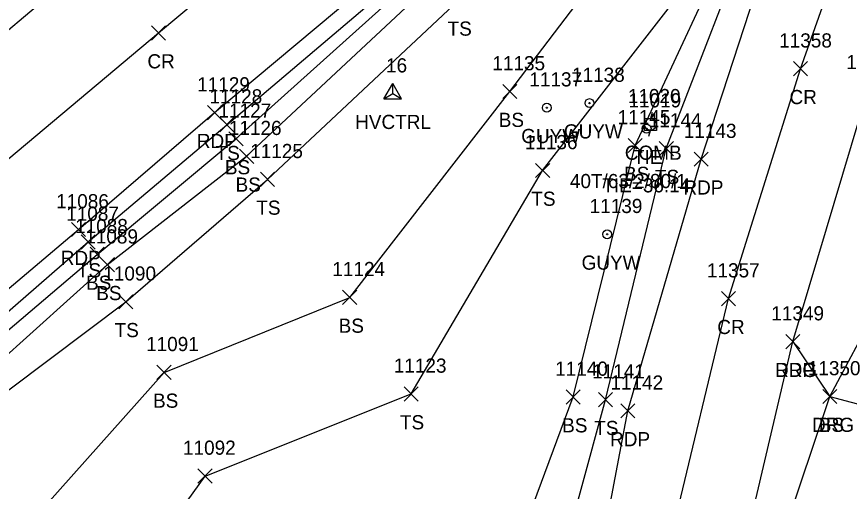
# Model space of a CAD drawing. Extents: x 1475671 to 1477951, y 592661 to 593821.
# Drawn here: x 1476740.9 to 1476858.4, y 593196.5 to 593263.5 of the extents above; entities that cross this region are included whole.
import ezdxf

# ---------------------------------------------------------------- set-up
doc = ezdxf.new("R2010")
doc.units = 0
for name, color, linetype in [('C_A', 7, 'Continuous'), ('C_C', 7, 'Continuous'), ('C_I', 7, 'Continuous'), ('CBP', 7, 'Continuous'), ('CPSM', 7, 'Continuous'), ('L_A', 7, 'Continuous'), ('L_I', 7, 'Continuous'), ('L_TIC', 7, 'Continuous'), ('LELB', 7, 'Continuous'), ('P_A', 7, 'Continuous'), ('P_I', 7, 'Continuous'), ('P_TIC', 7, 'Continuous'), ('PET', 7, 'Continuous'), ('PRC', 7, 'Continuous'), ('R_A', 7, 'Continuous'), ('R_I', 7, 'Continuous'), ('R_TIC', 7, 'Continuous'), ('RDG', 7, 'Continuous'), ('U_A', 7, 'Continuous'), ('U_C', 7, 'Continuous'), ('U_I', 7, 'Continuous'), ('UP', 7, 'Continuous'), ('UPGW', 7, 'Continuous')]:
    doc.layers.add(name, color=color, linetype=linetype)

msp = doc.modelspace()

# ---------------------------------------------------------------- linework, layer by layer
at = {"layer": 'CBP'}
for radius in [0.625, 0.0833]:
    msp.add_circle((1476829.76, 593247.7), radius, dxfattribs=at)
at = {"layer": 'CPSM'}
for p, q in [((1476792.7, 593251.92), (1476793.95, 593254.09)), ((1476792.7, 593251.92), (1476793.95, 593254.09)), ((1476792.7, 593251.92), (1476793.95, 593254.09)), ((1476792.7, 593251.92), (1476793.95, 593254.09)), ((1476792.7, 593251.92), (1476793.95, 593254.09)), ((1476792.7, 593251.92), (1476793.95, 593254.09)), ((1476792.7, 593251.92), (1476793.95, 593254.09)), ((1476792.7, 593251.92), (1476793.95, 593254.09)), ((1476795.2, 593251.92), (1476793.95, 593254.09)), ((1476793.95, 593252.65), (1476793.95, 593254.09)), ((1476795.2, 593251.92), (1476793.95, 593254.09)), ((1476793.95, 593252.65), (1476793.95, 593254.09)), ((1476795.2, 593251.92), (1476793.95, 593254.09)), ((1476793.95, 593252.65), (1476793.95, 593254.09)), ((1476795.2, 593251.92), (1476793.95, 593254.09)), ((1476793.95, 593252.65), (1476793.95, 593254.09)), ((1476795.2, 593251.92), (1476793.95, 593254.09)), ((1476793.95, 593252.65), (1476793.95, 593254.09)), ((1476795.2, 593251.92), (1476793.95, 593254.09)), ((1476793.95, 593252.65), (1476793.95, 593254.09)), ((1476795.2, 593251.92), (1476793.95, 593254.09)), ((1476793.95, 593252.65), (1476793.95, 593254.09)), ((1476795.2, 593251.92), (1476793.95, 593254.09)), ((1476793.95, 593252.65), (1476793.95, 593254.09)), ((1476792.7, 593251.92), (1476793.95, 593252.65)), ((1476792.7, 593251.92), (1476793.95, 593252.65)), ((1476792.7, 593251.92), (1476793.95, 593252.65)), ((1476792.7, 593251.92), (1476793.95, 593252.65)), ((1476792.7, 593251.92), (1476793.95, 593252.65)), ((1476792.7, 593251.92), (1476793.95, 593252.65)), ((1476792.7, 593251.92), (1476793.95, 593252.65)), ((1476792.7, 593251.92), (1476793.95, 593252.65)), ((1476792.7, 593251.92), (1476795.2, 593251.92)), ((1476792.7, 593251.92), (1476795.2, 593251.92)), ((1476792.7, 593251.92), (1476795.2, 593251.92)), ((1476792.7, 593251.92), (1476795.2, 593251.92)), ((1476792.7, 593251.92), (1476795.2, 593251.92)), ((1476792.7, 593251.92), (1476795.2, 593251.92)), ((1476792.7, 593251.92), (1476795.2, 593251.92)), ((1476792.7, 593251.92), (1476795.2, 593251.92)), ((1476793.95, 593252.65), (1476793.95, 593252.65)), ((1476793.95, 593252.65), (1476795.2, 593251.92)), ((1476793.95, 593252.65), (1476793.95, 593252.65)), ((1476793.95, 593252.65), (1476795.2, 593251.92)), ((1476793.95, 593252.65), (1476793.95, 593252.65)), ((1476793.95, 593252.65), (1476795.2, 593251.92)), ((1476793.95, 593252.65), (1476793.95, 593252.65)), ((1476793.95, 593252.65), (1476795.2, 593251.92)), ((1476793.95, 593252.65), (1476793.95, 593252.65)), ((1476793.95, 593252.65), (1476795.2, 593251.92)), ((1476793.95, 593252.65), (1476793.95, 593252.65)), ((1476793.95, 593252.65), (1476795.2, 593251.92)), ((1476793.95, 593252.65), (1476793.95, 593252.65)), ((1476793.95, 593252.65), (1476795.2, 593251.92)), ((1476793.95, 593252.65), (1476793.95, 593252.65)), ((1476793.95, 593252.65), (1476795.2, 593251.92))]:
    msp.add_line(p, q, dxfattribs=at)
at = {"layer": 'L_TIC'}
for points in [[(1476809.46, 593251.94), (1476811.46, 593253.94)], [(1476811.46, 593251.94), (1476809.46, 593253.94)], [(1476769.54, 593247.26), (1476771.54, 593249.26)], [(1476771.54, 593247.26), (1476769.54, 593249.26)], [(1476770.82, 593245.25), (1476772.82, 593247.25)], [(1476772.82, 593245.25), (1476770.82, 593247.25)], [(1476827.14, 593244.31), (1476829.14, 593246.31)], [(1476829.14, 593244.31), (1476827.14, 593246.31)], [(1476772.33, 593242.8), (1476774.33, 593244.8)], [(1476774.33, 593242.8), (1476772.33, 593244.8)], [(1476831.54, 593243.88), (1476833.54, 593245.88)], [(1476833.54, 593243.88), (1476831.54, 593245.88)], [(1476814.09, 593240.8), (1476816.09, 593242.8)], [(1476816.09, 593240.8), (1476814.09, 593242.8)], [(1476775.28, 593239.54), (1476777.28, 593241.54)], [(1476777.28, 593239.54), (1476775.28, 593241.54)], [(1476749.98, 593230.69), (1476751.98, 593232.69)], [(1476751.98, 593230.69), (1476749.98, 593232.69)], [(1476751.23, 593228.94), (1476753.23, 593230.94)], [(1476753.23, 593228.94), (1476751.23, 593230.94)], [(1476752.67, 593227.48), (1476754.67, 593229.48)], [(1476754.67, 593227.48), (1476752.67, 593229.48)], [(1476786.87, 593222.87), (1476788.87, 593224.87)], [(1476788.87, 593222.87), (1476786.87, 593224.87)], [(1476755.29, 593222.25), (1476757.29, 593224.25)], [(1476757.29, 593222.25), (1476755.29, 593224.25)], [(1476760.68, 593212.28), (1476762.68, 593214.28)], [(1476762.68, 593212.28), (1476760.68, 593214.28)], [(1476795.55, 593209.23), (1476797.55, 593211.23)], [(1476797.55, 593209.23), (1476795.55, 593211.23)], [(1476818.41, 593208.8), (1476820.41, 593210.8)], [(1476820.41, 593208.8), (1476818.41, 593210.8)], [(1476854.62, 593208.87), (1476856.62, 593210.87)], [(1476856.62, 593208.87), (1476854.62, 593210.87)], [(1476822.97, 593208.42), (1476824.97, 593210.42)], [(1476824.97, 593208.42), (1476822.97, 593210.42)], [(1476766.46, 593197.64), (1476768.46, 593199.64)], [(1476768.46, 593197.64), (1476766.46, 593199.64)]]:
    msp.add_lwpolyline(points, dxfattribs=at)
at = {"layer": 'LELB'}
for points in [[(1476844.89, 593161.77), (1476849.57, 593180.8), (1476849.13, 593190.54), (1476855.62, 593209.87), (1476862.35, 593222.47), (1476869.87, 593249.68), (1476878.56, 593271.73), (1476877.88, 593280.96), (1476889.82, 593301.6), (1476893.1, 593318.84), (1476908.59, 593341.2), (1476918.55, 593355.38), (1476919.84, 593361.76), (1476917.93, 593365.87), (1476921.61, 593367.66), (1476922.08, 593366.69), (1476922.63, 593360.35), (1476925.59, 593366.62)], [(1476564.12, 593090.41), (1476582.11, 593100.23), (1476611.48, 593121.39), (1476618.84, 593125.52), (1476623.35, 593128.86), (1476625.72, 593132.79), (1476629.36, 593135.67), (1476655.41, 593152.72), (1476679.21, 593171.49), (1476707, 593193.97), (1476724.55, 593208.7), (1476750.98, 593231.69), (1476770.54, 593248.26), (1476798.66, 593272.17), (1476825.82, 593296.2), (1476846.6, 593313.13), (1476851.35, 593312.9), (1476856.13, 593310.72)], [(1476716.34, 593096.61), (1476747.99, 593101.23), (1476767.4, 593103.17), (1476784.21, 593098.41), (1476795.95, 593095.07), (1476817.54, 593090.06), (1476823.68, 593097.1), (1476820.13, 593119.71), (1476817.83, 593141.9), (1476818.22, 593150.2), (1476818.44, 593161.48), (1476817.39, 593176.1), (1476816.81, 593183.14), (1476823.97, 593209.42), (1476832.54, 593244.88), (1476845.72, 593279.11), (1476851.19, 593296.52), (1476856.13, 593310.72)], [(1476634.2, 593131.94), (1476659.65, 593146.95), (1476682.12, 593166.73), (1476708.67, 593192.24), (1476725.71, 593207.35), (1476752.23, 593229.94), (1476771.82, 593246.25), (1476799.29, 593271), (1476827.81, 593293.85), (1476847.08, 593308.34), (1476849.31, 593306.85)], [(1476637.68, 593129.04), (1476661.51, 593144.5), (1476683.5, 593163.51), (1476710.24, 593189.5), (1476727.5, 593204.94), (1476753.67, 593228.48), (1476773.33, 593243.8), (1476800.69, 593269.42), (1476829.36, 593291.34), (1476849.31, 593306.85)], [(1476656.28, 593095.98), (1476668.8, 593096.98), (1476674.42, 593093.25), (1476681.71, 593092.91), (1476715.01, 593104.2), (1476743.41, 593111.46), (1476771.5, 593107.28), (1476782.77, 593105.35), (1476795.28, 593099.97), (1476811.26, 593100.05), (1476809.57, 593119.11), (1476813.36, 593153.77), (1476804.91, 593159.06), (1476804.56, 593163.8), (1476803.63, 593168.61), (1476810.96, 593186.98), (1476819.41, 593209.8), (1476828.14, 593245.31), (1476843.63, 593278.61), (1476845.71, 593295.92), (1476849.31, 593306.85)], [(1476678.64, 593101), (1476705.61, 593123.8), (1476726.04, 593155.11), (1476737.72, 593186.36), (1476761.68, 593213.28), (1476787.87, 593223.87), (1476810.46, 593252.94), (1476833.91, 593283.76), (1476845.71, 593295.92)], [(1476656.22, 593100.09), (1476649.63, 593114.77), (1476646.3, 593117.93), (1476646.01, 593122.62), (1476642.33, 593128.21), (1476662.9, 593142.59), (1476684.96, 593160.73), (1476712.65, 593184.75), (1476728.9, 593202.65), (1476756.29, 593223.25), (1476776.28, 593240.54), (1476803.27, 593265.83), (1476831.65, 593287.61)], [(1476678.64, 593101), (1476711, 593115.17), (1476731.22, 593143.42), (1476747.62, 593171.01), (1476767.46, 593198.64), (1476796.55, 593210.23), (1476815.09, 593241.8), (1476843.63, 593278.61)]]:
    msp.add_lwpolyline(points, dxfattribs=at)
at = {"layer": 'P_TIC'}
for points in [[(1476759.9, 593260.21), (1476761.9, 593262.21)], [(1476761.9, 593260.21), (1476759.9, 593262.21)], [(1476850.49, 593255.16), (1476852.49, 593257.16)], [(1476852.49, 593255.16), (1476850.49, 593257.16)], [(1476767.81, 593248.96), (1476769.81, 593250.96)], [(1476769.81, 593248.96), (1476767.81, 593250.96)], [(1476836.47, 593242.39), (1476838.47, 593244.39)], [(1476838.47, 593242.39), (1476836.47, 593244.39)], [(1476748.61, 593232.45), (1476750.61, 593234.45)], [(1476750.61, 593232.45), (1476748.61, 593234.45)], [(1476840.31, 593222.69), (1476842.31, 593224.69)], [(1476842.31, 593222.69), (1476840.31, 593224.69)], [(1476849.39, 593216.62), (1476851.39, 593218.62)], [(1476851.39, 593216.62), (1476849.39, 593218.62)], [(1476826.12, 593206.84), (1476828.12, 593208.84)], [(1476828.12, 593206.84), (1476826.12, 593208.84)]]:
    msp.add_lwpolyline(points, dxfattribs=at)
at = {"layer": 'PET'}
for points in [[(1476493.61, 593061.9), (1476518.9, 593073.26), (1476550.12, 593088.22), (1476579.1, 593105.35), (1476612.57, 593127.79), (1476627.64, 593138.01), (1476653.65, 593155.86), (1476677.37, 593174.62), (1476705.43, 593196.67), (1476722.66, 593210.69), (1476749.61, 593233.45), (1476768.81, 593249.96), (1476797.5, 593274.02), (1476824.82, 593297.55), (1476845, 593315.29), (1476868.19, 593333.86), (1476888.66, 593352.98), (1476918.01, 593376.95), (1476944.23, 593398.87), (1476967.73, 593418.7), (1476998.53, 593444.47)], [(1476459.25, 593078.48), (1476508.39, 593100.17), (1476518.15, 593105.13), (1476565.38, 593131.07), (1476607.43, 593157.45), (1476640.25, 593180.54), (1476678.21, 593210.57), (1476708.64, 593235.75), (1476725.67, 593249.83), (1476755.84, 593275.3), (1476786.3, 593300.73), (1476814.32, 593324.28), (1476845.05, 593350.02), (1476865.02, 593366.82), (1476897.04, 593395.14), (1476922.98, 593419.08), (1476952.36, 593443.37)], [(1476852.05, 593085.53), (1476845.73, 593108.15), (1476841.01, 593134.78), (1476840.06, 593162.08), (1476843.4, 593187.72), (1476850.39, 593217.62), (1476860.98, 593253.11), (1476864.6, 593261.54), (1476871.79, 593281.35), (1476880.28, 593307.27), (1476885.63, 593321.18), (1476897.83, 593348.03), (1476918.01, 593376.95)], [(1476550.12, 593088.22), (1476546.99, 593080.79), (1476546.62, 593074.3), (1476558.02, 593070.45), (1476566.6, 593070.83), (1476605.7, 593074.02), (1476651.65, 593078.89), (1476683.81, 593086.28), (1476716.78, 593091.72), (1476756.3, 593096.32), (1476786.76, 593094.61), (1476795.52, 593092.66), (1476816.88, 593085.29), (1476835.43, 593074.22), (1476828.62, 593102.02), (1476824.42, 593119.75), (1476821.59, 593140.77), (1476821.02, 593163.56), (1476821.92, 593180.44), (1476827.12, 593207.84), (1476837.47, 593243.39), (1476848.83, 593278.3), (1476858.44, 593303.19), (1476868.19, 593333.86)]]:
    msp.add_lwpolyline(points, dxfattribs=at)
at = {"layer": 'PRC'}
for points in [[(1476461.98, 593064.62), (1476520.7, 593090.52), (1476540.79, 593101.34), (1476577.67, 593121.61), (1476614.51, 593145.69), (1476649.36, 593170.81), (1476687.02, 593200.01), (1476716.69, 593224.25), (1476733.58, 593238.31), (1476760.9, 593261.21), (1476795.35, 593290.14), (1476823.06, 593313.51), (1476854.07, 593339.52), (1476875.7, 593357.51), (1476907.01, 593384.08), (1476934.06, 593407.68), (1476963.46, 593432.81)], [(1476853.41, 593046.52), (1476841.6, 593084.28), (1476835.78, 593107.15), (1476831.7, 593132.51), (1476830.84, 593162.78), (1476833.45, 593190.92), (1476841.31, 593223.69), (1476851.49, 593256.16), (1476861.32, 593283.91), (1476867.45, 593299.57), (1476876.22, 593323.15), (1476888.66, 593352.98)]]:
    msp.add_lwpolyline(points, dxfattribs=at)
at = {"layer": 'R_TIC'}
for points in [[(1476849.39, 593216.62), (1476851.39, 593218.62)], [(1476851.39, 593216.62), (1476849.39, 593218.62)], [(1476854.62, 593208.87), (1476856.62, 593210.87)], [(1476856.62, 593208.87), (1476854.62, 593210.87)]]:
    msp.add_lwpolyline(points, dxfattribs=at)
at = {"layer": 'RDG'}
msp.add_lwpolyline([(1476850.39, 593217.62), (1476855.62, 593209.87), (1476871.37, 593205.7), (1476882.63, 593203.65), (1476898.32, 593201.52), (1476908.1, 593203.87), (1476921.63, 593214.39), (1476929.61, 593231.45), (1476934.18, 593252.23), (1476938.78, 593270.03), (1476944.38, 593296.1), (1476944.94, 593325.58), (1476942.87, 593338.88), (1476933.5, 593367.74), (1476927.3, 593373.86), (1476918.01, 593376.95)], dxfattribs=at)
at = {"layer": 'UP'}
for p, q in [((1476830.56, 593249.96), (1476830.31, 593249.13)), ((1476829.47, 593247.46), (1476829.47, 593249.13)), ((1476829.47, 593249.13), (1476831.14, 593249.13)), ((1476830.31, 593248.3), (1476830.31, 593248.3)), ((1476831.14, 593249.13), (1476831.14, 593247.46)), ((1476831.14, 593247.46), (1476829.47, 593247.46)), ((1476830.06, 593246.63), (1476830.31, 593247.46))]:
    msp.add_line(p, q, dxfattribs=at)
msp.add_circle((1476830.31, 593248.3), 0.833, dxfattribs=at)
at = {"layer": 'UPGW'}
for centre, radius in [((1476821.7, 593251.31), 0.625), ((1476815.68, 593250.66), 0.625), ((1476815.68, 593250.66), 0.0833), ((1476821.7, 593251.31), 0.0833), ((1476824.2, 593232.78), 0.625), ((1476824.2, 593232.78), 0.0833)]:
    msp.add_circle(centre, radius, dxfattribs=at)

# ---------------------------------------------------------------- texts
at = {"layer": 'C_A'}
for s, p in [('HVCTRL', (1476788.64, 593247.65)), ('HVCTRL', (1476788.64, 593247.65)), ('HVCTRL', (1476788.64, 593247.65)), ('HVCTRL', (1476788.64, 593247.65)), ('HVCTRL', (1476788.64, 593247.65)), ('HVCTRL', (1476788.64, 593247.65)), ('HVCTRL', (1476788.64, 593247.65)), ('HVCTRL', (1476788.64, 593247.65)), ('TIE', (1476827.84, 593242.7))]:
    msp.add_text(s, height=2, dxfattribs=at).set_placement(p)
at = {"layer": 'C_C'}
msp.add_text('TIE=36.14', height=2, dxfattribs=at).set_placement((1476823.51, 593238.7))
at = {"layer": 'C_I'}
for s, p in [('16', (1476793, 593255.64)), ('16', (1476793, 593255.64)), ('16', (1476793, 593255.64)), ('16', (1476793, 593255.64)), ('16', (1476793, 593255.64)), ('16', (1476793, 593255.64)), ('16', (1476793, 593255.64)), ('16', (1476793, 593255.64)), ('11019', (1476827.21, 593250.7))]:
    msp.add_text(s, height=2, dxfattribs=at).set_placement(p)
at = {"layer": 'L_A'}
for s, p in [('TS', (1476801.68, 593260.83)), ('BS', (1476808.9, 593247.94)), ('TS', (1476768.95, 593243.26)), ('BS', (1476770.26, 593241.25)), ('BS', (1476826.58, 593240.31)), ('TS', (1476830.95, 593239.88)), ('BS', (1476771.77, 593238.8)), ('TS', (1476813.5, 593236.8)), ('TS', (1476774.69, 593235.54)), ('TS', (1476749.39, 593226.69)), ('BS', (1476750.67, 593224.94)), ('BS', (1476752.11, 593223.48)), ('TS', (1476754.7, 593218.25)), ('BS', (1476786.31, 593218.87)), ('BS', (1476760.12, 593208.28)), ('TS', (1476794.96, 593205.23)), ('BS', (1476817.85, 593204.8)), ('TS', (1476822.38, 593204.42)), ('BS', (1476854.06, 593204.87))]:
    msp.add_text(s, height=2, dxfattribs=at).set_placement(p)
at = {"layer": 'L_I'}
for s, p in [('11135', (1476808, 593255.94)), ('11128', (1476768.09, 593251.26)), ('11127', (1476769.36, 593249.25)), ('11145', (1476825.68, 593248.31)), ('11144', (1476830.08, 593247.88)), ('11126', (1476770.82, 593246.8)), ('11136', (1476812.58, 593244.8)), ('11125', (1476773.83, 593243.54)), ('11087', (1476747.87, 593234.69)), ('11088', (1476749.13, 593232.94)), ('11089', (1476750.56, 593231.48)), ('11090', (1476753.1, 593226.25)), ('11124', (1476785.42, 593226.87)), ('11091', (1476759.14, 593216.28)), ('11123', (1476794.09, 593213.23)), ('11140', (1476816.86, 593212.8)), ('11141', (1476822.08, 593212.42)), ('11350', (1476852.51, 593212.87)), ('11092', (1476764.35, 593201.64))]:
    msp.add_text(s, height=2, dxfattribs=at).set_placement(p)
at = {"layer": 'P_A'}
for s, p in [('CR', (1476759.33, 593256.21)), ('CR', (1476849.93, 593251.16)), ('RDP', (1476766.3, 593244.96)), ('RDP', (1476834.96, 593238.39)), ('RDP', (1476747.1, 593228.45)), ('CR', (1476839.74, 593218.69)), ('RDP', (1476847.88, 593212.62)), ('RDP', (1476824.61, 593202.84))]:
    msp.add_text(s, height=2, dxfattribs=at).set_placement(p)
at = {"layer": 'P_I'}
for s, p in [('11358', (1476848.47, 593259.16)), ('11359', (1476857.95, 593256.11)), ('11129', (1476766.35, 593252.96)), ('11143', (1476835.01, 593246.39)), ('11086', (1476746.45, 593236.45)), ('11357', (1476838.28, 593226.69)), ('11349', (1476847.36, 593220.62)), ('11142', (1476824.66, 593210.84))]:
    msp.add_text(s, height=2, dxfattribs=at).set_placement(p)
at = {"layer": 'R_A'}
for p in [(1476847.88, 593212.62), (1476853.11, 593204.87)]:
    msp.add_text('DRG', height=2, dxfattribs=at).set_placement(p)
at = {"layer": 'R_I'}
for s, p in [('11349', (1476847.36, 593220.62)), ('11350', (1476852.51, 593212.87))]:
    msp.add_text(s, height=2, dxfattribs=at).set_placement(p)
at = {"layer": 'U_A'}
for s, p in [('GUYW', (1476818.09, 593246.31)), ('GUYW', (1476812.07, 593245.66)), ('COMB', (1476826.69, 593243.3)), ('GUYW', (1476820.59, 593227.78))]:
    msp.add_text(s, height=2, dxfattribs=at).set_placement(p)
at = {"layer": 'U_C'}
msp.add_text('40T/63/2/80/1', height=2, dxfattribs=at).set_placement((1476818.94, 593239.3))
at = {"layer": 'U_I'}
for s, p in [('11137', (1476813.22, 593253.66)), ('11138', (1476819.24, 593254.31)), ('11020', (1476827.12, 593251.3)), ('11139', (1476821.73, 593235.78))]:
    msp.add_text(s, height=2, dxfattribs=at).set_placement(p)

doc.saveas('drawing.dxf')
